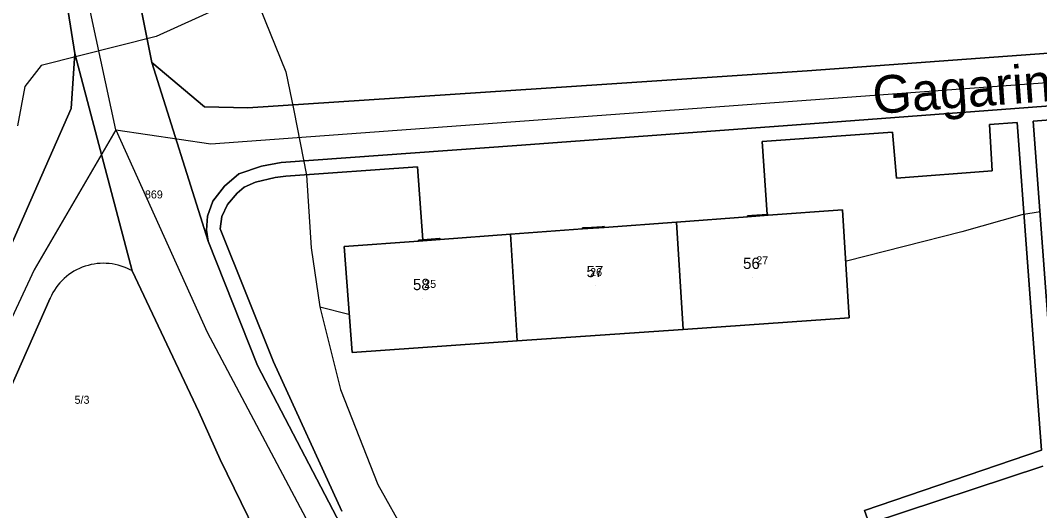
# Model space of a CAD drawing. Extents: x -873642 to -872917, y -1012962 to -1012567.
# Drawn here: x -873481.3 to -873373.1, y -1012747.9 to -1012695.8 of the extents above; entities that cross this region are included whole.
import ezdxf

# ---------------------------------------------------------------- set-up
doc = ezdxf.new("R2010")
doc.units = 0
for name, color, linetype in [('adresni_misto', 7, 'Continuous'), ('cisla_parcelni_kn', 7, 'Continuous'), ('cislo_domovni', 7, 'Continuous'), ('osy_ulic', 7, 'Continuous'), ('parcely_kn', 7, 'Continuous'), ('stavebni_objekty_bydleni', 7, 'Continuous'), ('TRASY - zamereno', 7, 'Continuous'), ('ulice', 7, 'Continuous')]:
    doc.layers.add(name, color=color, linetype=linetype)

msp = doc.modelspace()

# ---------------------------------------------------------------- linework, layer by layer
at = {"layer": 'adresni_misto'}
for p, q in [((-873403.56, -1012723.13), (-873403.56, -1012723.13)), ((-873420.19, -1012724), (-873420.19, -1012724)), ((-873438.63, -1012725.38), (-873438.63, -1012725.38))]:
    msp.add_line(p, q, dxfattribs=at)
at = {"layer": 'osy_ulic'}
for points in [[(-873471.18, -1012707.47), (-873474.38, -1012692.61), (-873476.15, -1012680.62), (-873478.28, -1012662.13), (-873481.95, -1012629.68), (-873573.16, -1012636.54), (-873602.96, -1012638.78)], [(-873471.18, -1012707.47), (-873461.09, -1012708.93), (-873257.79, -1012694.05), (-873080.41, -1012681.66)], [(-873471.18, -1012707.47), (-873479.88, -1012722.32), (-873510.54, -1012788.14), (-873541.44, -1012862.33), (-873570.51, -1012920.68), (-873579.23, -1012922.87)], [(-873471.18, -1012707.47), (-873461.48, -1012728.93), (-873411.85, -1012822.53)]]:
    msp.add_lwpolyline(points, dxfattribs=at)
at = {"layer": 'parcely_kn'}
for points in [[(-873095.85, -1012678.72), (-873263.61, -1012691.39), (-873266.56, -1012691.78), (-873320.85, -1012695.55), (-873397.76, -1012701.2), (-873419.57, -1012702.63), (-873457.18, -1012705.12), (-873461.77, -1012705), (-873467.35, -1012700.29), (-873470.31, -1012685.53), (-873471.34, -1012679.34), (-873473.95, -1012664.84), (-873474.55, -1012659.21), (-873476.91, -1012642.49), (-873476.25, -1012638.16), (-873474.09, -1012635.88), (-873470.15, -1012634.51), (-873407.08, -1012629.93)], [(-873095.85, -1012678.72), (-873263.61, -1012691.39), (-873266.56, -1012691.78), (-873320.85, -1012695.55), (-873397.76, -1012701.2), (-873419.57, -1012702.63), (-873457.18, -1012705.12), (-873461.77, -1012705), (-873467.35, -1012700.29), (-873470.31, -1012685.53), (-873471.34, -1012679.34), (-873473.95, -1012664.84), (-873474.55, -1012659.21), (-873476.91, -1012642.49), (-873476.25, -1012638.16), (-873474.09, -1012635.88), (-873470.15, -1012634.51), (-873407.08, -1012629.93)], [(-873492.26, -1012636.3), (-873470.15, -1012634.51), (-873474.09, -1012635.88), (-873476.25, -1012638.16), (-873476.91, -1012642.49), (-873474.55, -1012659.21), (-873473.95, -1012664.84), (-873471.34, -1012679.34), (-873470.31, -1012685.53), (-873467.35, -1012700.29), (-873461.39, -1012719.27), (-873456.13, -1012732.5), (-873430.5, -1012781.58), (-873414.44, -1012810.45), (-873408.91, -1012815.19), (-873407.03, -1012815.83), (-873405.77, -1012816.17), (-873403.3, -1012816.28), (-873400.05, -1012815.37), (-873370.19, -1012803.49), (-873353.25, -1012796.68), (-873342.17, -1012792.27), (-873320.46, -1012784.28)], [(-873492.26, -1012636.3), (-873470.15, -1012634.51), (-873474.09, -1012635.88), (-873476.25, -1012638.16), (-873476.91, -1012642.49), (-873474.55, -1012659.21), (-873473.95, -1012664.84), (-873471.34, -1012679.34), (-873470.31, -1012685.53), (-873467.35, -1012700.29), (-873461.39, -1012719.27), (-873456.13, -1012732.5), (-873430.5, -1012781.58), (-873414.44, -1012810.45), (-873408.91, -1012815.19), (-873407.03, -1012815.83), (-873405.77, -1012816.17), (-873403.3, -1012816.28), (-873400.05, -1012815.37), (-873370.19, -1012803.49), (-873353.25, -1012796.68), (-873342.17, -1012792.27), (-873320.46, -1012784.28)], [(-873484.65, -1012640.59), (-873481.33, -1012666.04), (-873477.8, -1012685.05), (-873475.56, -1012699.33), (-873475.94, -1012705.18), (-873480.6, -1012715.8), (-873485.41, -1012726.76)], [(-873484.65, -1012640.59), (-873481.33, -1012666.04), (-873477.8, -1012685.05), (-873475.56, -1012699.33), (-873475.94, -1012705.18), (-873480.6, -1012715.8), (-873485.41, -1012726.76)], [(-873267.15, -1012775.08), (-873296.21, -1012784.7), (-873317.65, -1012791.79), (-873327.22, -1012794.59), (-873352.28, -1012804.24), (-873370.67, -1012811.62), (-873407.44, -1012826.19), (-873420.81, -1012815.05), (-873432.2, -1012793.89), (-873433.76, -1012792.56), (-873435.3, -1012792.45), (-873437.28, -1012792.66), (-873438.97, -1012789.6), (-873437.44, -1012788.27), (-873436.61, -1012786.86), (-873438.55, -1012783.17), (-873447.85, -1012766.32), (-873454.18, -1012754.58), (-873460.09, -1012742.48), (-873462.37, -1012737.41), (-873469.44, -1012722.44), (-873475.56, -1012699.33), (-873477.8, -1012685.05)], [(-873267.15, -1012775.08), (-873296.21, -1012784.7), (-873317.65, -1012791.79), (-873327.22, -1012794.59), (-873352.28, -1012804.24), (-873370.67, -1012811.62), (-873407.44, -1012826.19), (-873420.81, -1012815.05), (-873432.2, -1012793.89), (-873433.76, -1012792.56), (-873435.3, -1012792.45), (-873437.28, -1012792.66), (-873438.97, -1012789.6), (-873437.44, -1012788.27), (-873436.61, -1012786.86), (-873438.55, -1012783.17), (-873447.85, -1012766.32), (-873454.18, -1012754.58), (-873460.09, -1012742.48), (-873462.37, -1012737.41), (-873469.44, -1012722.44), (-873475.56, -1012699.33), (-873477.8, -1012685.05)], [(-873266.47, -1012697.2), (-873295.44, -1012699.37), (-873352.55, -1012703.45), (-873395.53, -1012706.69), (-873428.59, -1012709.13), (-873453.64, -1012710.91), (-873455.72, -1012711.3), (-873458.12, -1012712.14), (-873459.66, -1012713.44), (-873460.89, -1012715.04), (-873461.46, -1012716.61), (-873461.56, -1012718.11), (-873461.39, -1012719.27), (-873467.35, -1012700.29), (-873461.77, -1012705), (-873457.18, -1012705.12), (-873419.57, -1012702.63), (-873397.76, -1012701.2), (-873320.85, -1012695.55), (-873266.56, -1012691.78)], [(-873266.47, -1012697.2), (-873295.44, -1012699.37), (-873352.55, -1012703.45), (-873395.53, -1012706.69), (-873428.59, -1012709.13), (-873453.64, -1012710.91), (-873455.72, -1012711.3), (-873458.12, -1012712.14), (-873459.66, -1012713.44), (-873460.89, -1012715.04), (-873461.46, -1012716.61), (-873461.56, -1012718.11), (-873461.39, -1012719.27), (-873467.35, -1012700.29), (-873461.77, -1012705), (-873457.18, -1012705.12), (-873419.57, -1012702.63), (-873397.76, -1012701.2), (-873320.85, -1012695.55), (-873266.56, -1012691.78)], [(-873527.42, -1012820.15), (-873519.1, -1012801.44), (-873512.71, -1012786.25), (-873510.44, -1012781.52), (-873506.07, -1012772.44), (-873503.65, -1012767.42), (-873487.34, -1012731.06), (-873485.41, -1012726.76), (-873480.6, -1012715.8), (-873475.94, -1012705.18), (-873475.56, -1012699.33), (-873469.44, -1012722.44)], [(-873527.42, -1012820.15), (-873519.1, -1012801.44), (-873512.71, -1012786.25), (-873510.44, -1012781.52), (-873506.07, -1012772.44), (-873503.65, -1012767.42), (-873487.34, -1012731.06), (-873485.41, -1012726.76), (-873480.6, -1012715.8), (-873475.94, -1012705.18), (-873475.56, -1012699.33), (-873469.44, -1012722.44)], [(-873430.5, -1012781.58), (-873456.13, -1012732.5), (-873461.39, -1012719.27), (-873461.56, -1012718.11), (-873461.46, -1012716.61), (-873460.89, -1012715.04), (-873459.66, -1012713.44), (-873458.12, -1012712.14), (-873455.72, -1012711.3), (-873453.64, -1012710.91), (-873428.59, -1012709.13), (-873395.53, -1012706.69), (-873352.55, -1012703.45)], [(-873430.5, -1012781.58), (-873456.13, -1012732.5), (-873461.39, -1012719.27), (-873461.56, -1012718.11), (-873461.46, -1012716.61), (-873460.89, -1012715.04), (-873459.66, -1012713.44), (-873458.12, -1012712.14), (-873455.72, -1012711.3), (-873453.64, -1012710.91), (-873428.59, -1012709.13), (-873395.53, -1012706.69), (-873352.55, -1012703.45)], [(-873371.72, -1012733.69), (-873373.75, -1012706.54), (-873360.86, -1012705.54)], [(-873360.86, -1012705.54), (-873373.75, -1012706.54), (-873371.72, -1012733.69)], [(-873371.72, -1012733.69), (-873373.75, -1012706.54), (-873360.86, -1012705.54)], [(-873360.86, -1012705.54), (-873373.75, -1012706.54), (-873371.72, -1012733.69)], [(-873447.17, -1012747.96), (-873454.45, -1012732.08), (-873460.1, -1012717.98), (-873459.94, -1012716.66), (-873459.31, -1012715.38), (-873458.3, -1012714.17), (-873457.55, -1012713.54), (-873456.37, -1012713.01), (-873454.26, -1012712.5), (-873453.14, -1012712.38), (-873439.14, -1012711.38), (-873438.56, -1012719.13), (-873439.05, -1012719.17), (-873439.04, -1012719.27), (-873446.92, -1012719.85), (-873446.1, -1012731.09), (-873428.55, -1012729.87), (-873410.91, -1012728.65), (-873393.28, -1012727.43), (-873393.98, -1012715.95), (-873401.88, -1012716.53), (-873401.88, -1012716.43), (-873401.99, -1012716.44), (-873402.53, -1012708.69), (-873388.7, -1012707.69), (-873388.26, -1012712.57), (-873378.08, -1012711.81), (-873378.37, -1012706.87), (-873375.45, -1012706.67), (-873373.38, -1012734.43), (-873372.85, -1012741.46), (-873391.67, -1012747.88), (-873391.16, -1012749.27), (-873372.72, -1012743.18)], [(-873372.72, -1012743.18), (-873391.16, -1012749.27), (-873391.67, -1012747.88), (-873372.85, -1012741.46), (-873373.38, -1012734.43), (-873375.45, -1012706.67), (-873378.37, -1012706.87), (-873378.08, -1012711.81), (-873388.26, -1012712.57), (-873388.7, -1012707.69), (-873402.53, -1012708.69), (-873401.99, -1012716.44), (-873403.64, -1012716.56), (-873404.08, -1012716.59), (-873404.07, -1012716.69), (-873411.63, -1012717.25), (-873419.3, -1012717.82), (-873419.31, -1012717.72), (-873419.53, -1012717.74), (-873421.22, -1012717.85), (-873421.6, -1012717.88), (-873421.6, -1012717.98), (-873429.27, -1012718.55), (-873436.75, -1012719.1), (-873436.76, -1012719), (-873436.81, -1012719), (-873438.56, -1012719.13), (-873439.14, -1012711.38), (-873453.14, -1012712.38), (-873454.26, -1012712.5), (-873456.37, -1012713.01), (-873457.55, -1012713.54), (-873458.3, -1012714.17), (-873459.31, -1012715.38), (-873459.94, -1012716.66), (-873460.1, -1012717.98), (-873454.45, -1012732.08), (-873447.17, -1012747.96)], [(-873447.17, -1012747.96), (-873454.45, -1012732.08), (-873460.1, -1012717.98), (-873459.94, -1012716.66), (-873459.31, -1012715.38), (-873458.3, -1012714.17), (-873457.55, -1012713.54), (-873456.37, -1012713.01), (-873454.26, -1012712.5), (-873453.14, -1012712.38), (-873439.14, -1012711.38), (-873438.56, -1012719.13), (-873439.05, -1012719.17), (-873439.04, -1012719.27), (-873446.92, -1012719.85), (-873446.1, -1012731.09), (-873428.55, -1012729.87), (-873410.91, -1012728.65), (-873393.28, -1012727.43), (-873393.98, -1012715.95), (-873401.88, -1012716.53), (-873401.88, -1012716.43), (-873401.99, -1012716.44), (-873402.53, -1012708.69), (-873388.7, -1012707.69), (-873388.26, -1012712.57), (-873378.08, -1012711.81), (-873378.37, -1012706.87), (-873375.45, -1012706.67), (-873373.38, -1012734.43), (-873372.85, -1012741.46), (-873391.67, -1012747.88), (-873391.16, -1012749.27), (-873372.72, -1012743.18)], [(-873372.72, -1012743.18), (-873391.16, -1012749.27), (-873391.67, -1012747.88), (-873372.85, -1012741.46), (-873373.38, -1012734.43), (-873375.45, -1012706.67), (-873378.37, -1012706.87), (-873378.08, -1012711.81), (-873388.26, -1012712.57), (-873388.7, -1012707.69), (-873402.53, -1012708.69), (-873401.99, -1012716.44), (-873403.64, -1012716.56), (-873404.08, -1012716.59), (-873404.07, -1012716.69), (-873411.63, -1012717.25), (-873419.3, -1012717.82), (-873419.31, -1012717.72), (-873419.53, -1012717.74), (-873421.22, -1012717.85), (-873421.6, -1012717.88), (-873421.6, -1012717.98), (-873429.27, -1012718.55), (-873436.75, -1012719.1), (-873436.76, -1012719), (-873436.81, -1012719), (-873438.56, -1012719.13), (-873439.14, -1012711.38), (-873453.14, -1012712.38), (-873454.26, -1012712.5), (-873456.37, -1012713.01), (-873457.55, -1012713.54), (-873458.3, -1012714.17), (-873459.31, -1012715.38), (-873459.94, -1012716.66), (-873460.1, -1012717.98), (-873454.45, -1012732.08), (-873447.17, -1012747.96)], [(-873469.44, -1012722.44), (-873462.37, -1012737.41), (-873460.09, -1012742.48), (-873454.18, -1012754.58), (-873447.85, -1012766.32), (-873438.55, -1012783.17), (-873498.44, -1012787.82), (-873499.25, -1012788.65), (-873498.73, -1012794.57), (-873498.47, -1012798.05), (-873510.35, -1012799.3), (-873495.72, -1012765.36), (-873494.38, -1012762.24), (-873490.76, -1012753.79), (-873478.18, -1012725.33)], [(-873469.44, -1012722.44), (-873462.37, -1012737.41), (-873460.09, -1012742.48), (-873454.18, -1012754.58), (-873447.85, -1012766.32), (-873438.55, -1012783.17), (-873498.44, -1012787.82), (-873499.25, -1012788.65), (-873498.73, -1012794.57), (-873498.47, -1012798.05), (-873510.35, -1012799.3), (-873495.72, -1012765.36), (-873494.38, -1012762.24), (-873490.76, -1012753.79), (-873478.18, -1012725.33)], [(-873478.18, -1012725.33), (-873490.76, -1012753.79)], [(-873478.18, -1012725.33), (-873490.76, -1012753.79)]]:
    msp.add_lwpolyline(points, dxfattribs=at)
for points in [[(-873393.98, -1012715.95), (-873393.28, -1012727.43), (-873410.91, -1012728.65), (-873411.63, -1012717.25), (-873404.07, -1012716.69), (-873404.08, -1012716.59), (-873403.64, -1012716.56), (-873401.99, -1012716.44), (-873401.88, -1012716.43), (-873401.88, -1012716.53)], [(-873393.98, -1012715.95), (-873393.28, -1012727.43), (-873410.91, -1012728.65), (-873411.63, -1012717.25), (-873404.07, -1012716.69), (-873404.08, -1012716.59), (-873403.64, -1012716.56), (-873401.99, -1012716.44), (-873401.88, -1012716.43), (-873401.88, -1012716.53)], [(-873411.63, -1012717.25), (-873410.91, -1012728.65), (-873428.55, -1012729.87), (-873429.27, -1012718.55), (-873421.6, -1012717.98), (-873421.6, -1012717.88), (-873421.22, -1012717.85), (-873419.53, -1012717.74), (-873419.31, -1012717.72), (-873419.3, -1012717.82)], [(-873411.63, -1012717.25), (-873410.91, -1012728.65), (-873428.55, -1012729.87), (-873429.27, -1012718.55), (-873421.6, -1012717.98), (-873421.6, -1012717.88), (-873421.22, -1012717.85), (-873419.53, -1012717.74), (-873419.31, -1012717.72), (-873419.3, -1012717.82)], [(-873429.27, -1012718.55), (-873428.55, -1012729.87), (-873446.1, -1012731.09), (-873446.92, -1012719.85), (-873439.04, -1012719.27), (-873439.05, -1012719.17), (-873438.56, -1012719.13), (-873436.81, -1012719), (-873436.76, -1012719), (-873436.75, -1012719.1)], [(-873429.27, -1012718.55), (-873428.55, -1012729.87), (-873446.1, -1012731.09), (-873446.92, -1012719.85), (-873439.04, -1012719.27), (-873439.05, -1012719.17), (-873438.56, -1012719.13), (-873436.81, -1012719), (-873436.76, -1012719), (-873436.75, -1012719.1)]]:
    msp.add_lwpolyline(points, close=True, dxfattribs=at)
for end in [156.1591, 156.1592, 156.1591, 156.1592]:
    msp.add_arc((-873472.5, -1012727.84), 6.21, 60.4352, end, dxfattribs=at)
at = {"layer": 'stavebni_objekty_bydleni'}
msp.add_lwpolyline([(-873421.6, -1012717.98), (-873419.3, -1012717.82), (-873411.63, -1012717.25), (-873404.07, -1012716.69), (-873401.88, -1012716.53), (-873393.98, -1012715.95), (-873393.28, -1012727.43), (-873410.91, -1012728.65), (-873428.55, -1012729.87), (-873446.1, -1012731.09), (-873446.92, -1012719.85), (-873439.04, -1012719.27), (-873436.75, -1012719.1), (-873429.27, -1012718.55)], close=True, dxfattribs=at)
at = {"layer": 'TRASY - zamereno'}
for p, q in [((-873460.09, -1012694.46), (-873466.89, -1012697.55)), ((-873455.92, -1012694.38), (-873453.14, -1012701.31)), ((-873466.89, -1012697.55), (-873479.12, -1012700.62)), ((-873479.12, -1012700.62), (-873480.86, -1012702.84)), ((-873453.14, -1012701.31), (-873452.27, -1012705.41)), ((-873480.86, -1012702.84), (-873481.63, -1012707.04)), ((-873452.27, -1012705.41), (-873450.95, -1012712.26)), ((-873450.95, -1012712.26), (-873450.44, -1012719.98)), ((-873374.94, -1012716.48), (-873381.31, -1012718.29)), ((-873372.98, -1012716.15), (-873374.94, -1012716.48)), ((-873381.31, -1012718.29), (-873393.57, -1012721.42)), ((-873450.44, -1012719.98), (-873449.53, -1012726.26)), ((-873449.53, -1012726.26), (-873447.33, -1012735.02)), ((-873449.53, -1012726.26), (-873446.45, -1012727.02)), ((-873447.33, -1012735.02), (-873443.35, -1012745.12)), ((-873443.35, -1012745.12), (-873437.27, -1012755.9))]:
    msp.add_line(p, q, dxfattribs=at)

# ---------------------------------------------------------------- texts
at = {"layer": 'cisla_parcelni_kn'}
for s, p in [('869', (-873468.1, -1012714.74)), ('869', (-873468.1, -1012714.74)), ('27', (-873403.15, -1012721.74)), ('27', (-873403.15, -1012721.74)), ('26', (-873420.8, -1012722.99)), ('26', (-873420.8, -1012722.99)), ('25', (-873438.43, -1012724.24)), ('25', (-873438.43, -1012724.24)), ('5/3', (-873475.57, -1012736.55)), ('5/3', (-873475.57, -1012736.55))]:
    msp.add_text(s, height=0.85, dxfattribs=at).set_placement(p)
at = {"layer": 'cislo_domovni'}
for s, p in [('57', (-873421.19, -1012723.1)), ('56', (-873404.56, -1012722.23)), ('58', (-873439.63, -1012724.48))]:
    msp.add_text(s, height=1.2, dxfattribs=at).set_placement(p)
at = {"layer": 'ulice'}
msp.add_text('Gagarinova', height=4, rotation=4.1861, dxfattribs=at).set_placement((-873390.66, -1012705.78))

doc.saveas('drawing.dxf')
